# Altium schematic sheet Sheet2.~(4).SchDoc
size A3
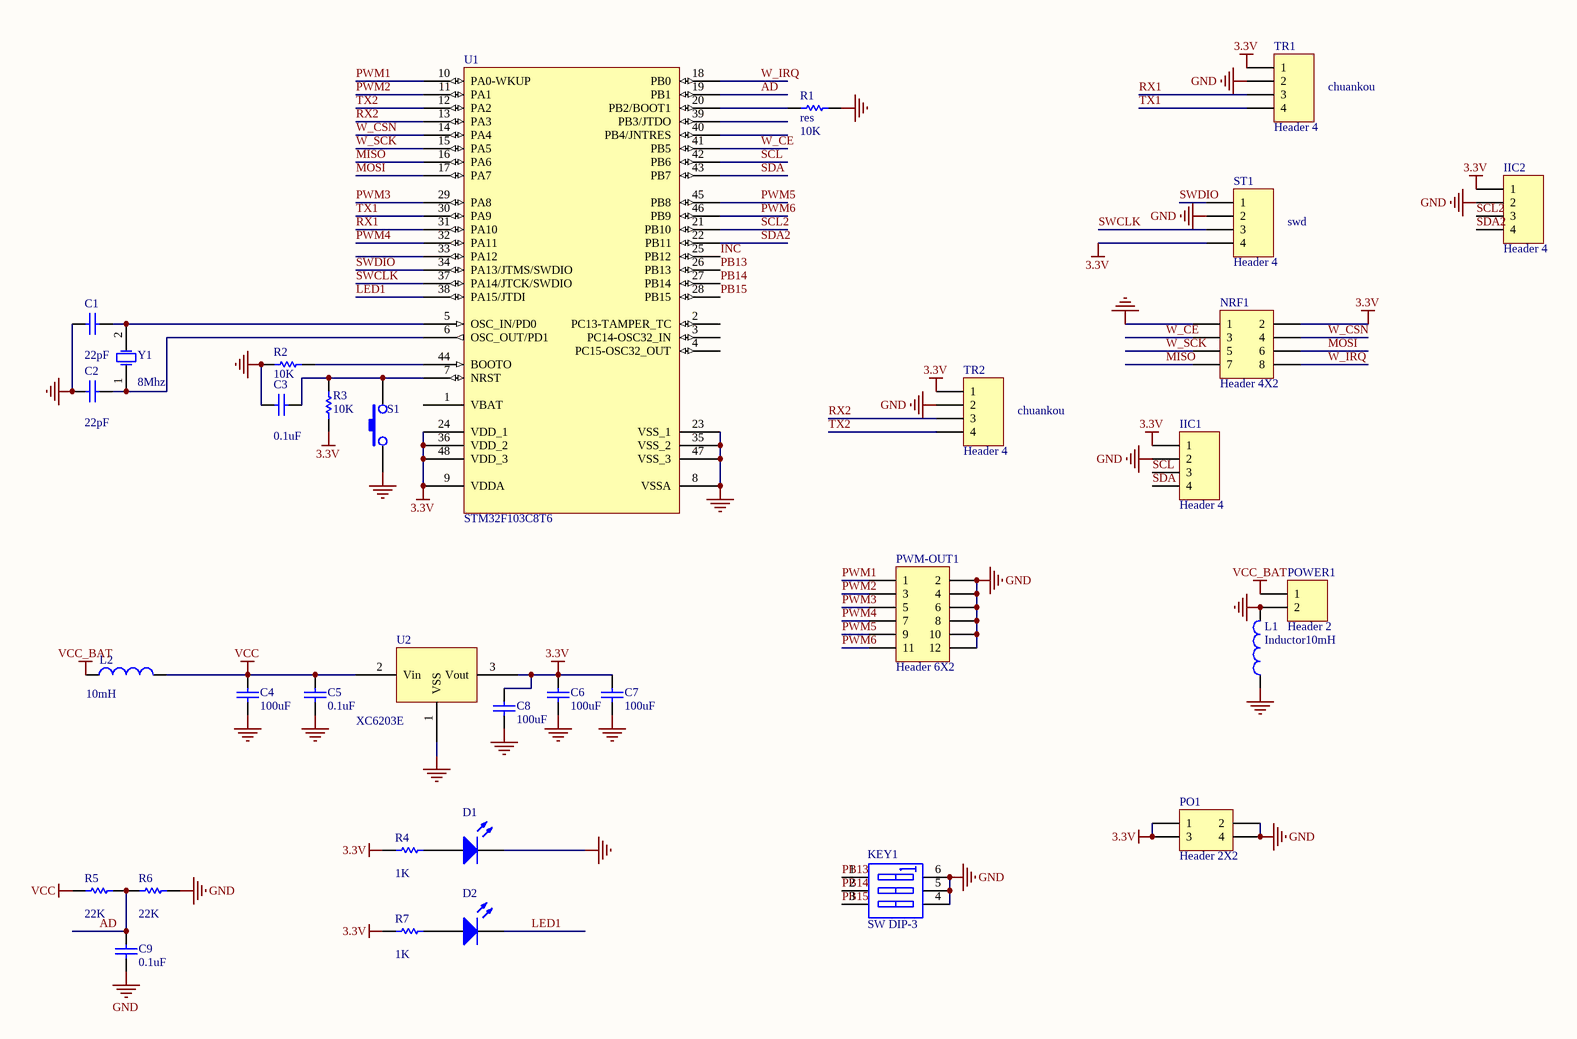
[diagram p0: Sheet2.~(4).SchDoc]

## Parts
C1  value 22pF  [0603]  (hidden comment: cap)
C2  value 22pF  [0603]  (hidden comment: cap)
C3  value 0.1uF  [0603]  (hidden comment: cap)
C4  value 100uF  [0603]  (hidden comment: cap)
C5  value 0.1uF  [0603]  (hidden comment: cap)
C6  value 100uF  [0603]  (hidden comment: cap)
C7  value 100uF  [0603]  (hidden comment: cap)
C8  value 100uF  [0603]  (hidden comment: cap)
C9  value 0.1uF  [0603]  (hidden comment: cap)
D1  LED0  [0603]  (value not drawn)
D2  LED0  [0603]  (value not drawn)
IIC1  Header 4  [HDR1X4]
IIC2  Header 4  [HDR1X4]
KEY1  SW DIP-3  [DIP6]
L1  Inductor10mH  [0805]
L2  value 10mH  [0805]  (hidden comment: Inductor)
NRF1  Header 4X2  [HDR2X4]
PO1  Header 2X2  [HDR2X2]
POWER1  Header 2  [HDR1X2]
PWM-OUT1  Header 6X2  [HDR2X6]
R1  res  res: 10K  [0603]
R2  res: 10K  [0603]  (hidden comment: res)
R3  res: 10K  [0603]  (hidden comment: res)
R4  res: 1K  [0603]  (hidden comment: res)
R5  res: 22K  [0603]  (hidden comment: res)
R6  res: 22K  [0603]  (hidden comment: res)
R7  res: 1K  [0603]  (hidden comment: res)
S1  (no value)  [7243]
ST1  Header 4  [HDR1X4]
TR1  Header 4  [HDR1X4]
TR2  Header 4  [HDR1X4]
U1  STM32F103C8T6  [LQFP48S]
U2  XC6203E  [SOT-89]
Y1  5032xtal  [XTAL]  (value not drawn)

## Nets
3.3V: C6.2 C7.2 C8.2 IIC1.1 IIC2.1 NRF1.2 PO1.1 PO1.3 R3.1 R4.1 R7.1 ST1.4 TR1.1 TR2.1 U1.9(VDDA) U1.24(VDD_1) U1.36(VDD_2) U1.48(VDD_3) U2.3(Vout)
GND: C1.1 C2.1 C3.1 C4.1 C5.1 C6.1 C7.1 C8.1 C9.1 D1.2(K) IIC1.2 IIC2.2 KEY1.4(B3) KEY1.5(B2) KEY1.6(B1) L1.1 L1.2 NRF1.1 PO1.2 PO1.4 POWER1.2 PWM-OUT1.2 PWM-OUT1.4 PWM-OUT1.6 PWM-OUT1.8 PWM-OUT1.10 PWM-OUT1.12 R1.2 R2.1 R6.2 S1.1 ST1.2 TR1.2 TR2.2 U1.8(VSSA) U1.23(VSS_1) U1.35(VSS_2) U1.47(VSS_3) U2.1(VSS)
VCC: C4.2 C5.2 L2.2 R5.1 U2.2(Vin)
VCC_BAT: L2.1 POWER1.1
AD: C9.2 R5.2 R6.1 U1.19(PB1)
INC: U1.25(PB12)
LED1: D2.2(K) U1.38(PA15/JTDI)
MISO: NRF1.7 U1.16(PA6)
MOSI: NRF1.6 U1.17(PA7)
PB13: KEY1.1(A1) U1.26(PB13)
PB14: KEY1.2(A2) U1.27(PB14)
PB15: KEY1.3(A3) U1.28(PB15)
PWM1: PWM-OUT1.1 U1.10(PA0-WKUP)
PWM2: PWM-OUT1.3 U1.11(PA1)
PWM3: PWM-OUT1.5 U1.29(PA8)
PWM4: PWM-OUT1.7 U1.32(PA11)
PWM5: PWM-OUT1.9 U1.45(PB8)
PWM6: PWM-OUT1.11 U1.46(PB9)
RX1: TR1.3 U1.31(PA10)
RX2: TR2.3 U1.13(PA3)
SCL: IIC1.3 U1.42(PB6)
SCL2: IIC2.3 U1.21(PB10)
SDA: IIC1.4 U1.43(PB7)
SDA2: IIC2.4 U1.22(PB11)
SWCLK: ST1.3 U1.37(PA14/JTCK/SWDIO)
SWDIO: ST1.1 U1.34(PA13/JTMS/SWDIO)
TX1: TR1.4 U1.30(PA9)
TX2: TR2.4 U1.12(PA2)
W_CE: NRF1.3 U1.41(PB5)
W_CSN: NRF1.4 U1.14(PA4)
W_IRQ: NRF1.8 U1.18(PB0)
W_SCK: NRF1.5 U1.15(PA5)
NetC1_2: C1.2 U1.5(OSC_IN/PD0) Y1.2(OSC2)
NetC2_2: C2.2 U1.6(OSC_OUT/PD1) Y1.1(OSC1)
NetC3_2: C3.2 R3.2 S1.2 U1.7(NRST)
NetD1_1: D1.1(A) R4.2
NetD2_1: D2.1(A) R7.2
NetR1_1: R1.1 U1.20(PB2/BOOT1)
NetR2_2: R2.2 U1.44(BOOTO)

Not connected (* = marked no-connect by the designer): U1 1(VBAT) 2(PC13-TAMPER_TC) 3(PC14-OSC32_IN) 4(PC15-OSC32_OUT) 33(PA12) 39(PB3/JTDO) 40(PB4/JNTRES)

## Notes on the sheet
- chuankou
- swd

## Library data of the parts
D1 D2 = LED0: Typical INFRARED GaAs LED
IIC1 IIC2 ST1 TR1 TR2 = Header 4: Header, 4-Pin
KEY1 = SW DIP-3: DIP Switch
L1 = Inductor
NRF1 = Header 4X2: Header, 4-Pin, Dual row
PO1 = Header 2X2: Header, 2-Pin, Dual row
POWER1 = Header 2: Header, 2-Pin
PWM-OUT1 = Header 6X2: Header, 6-Pin, Dual row
S1 = 微动开关
U2 = XC6203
